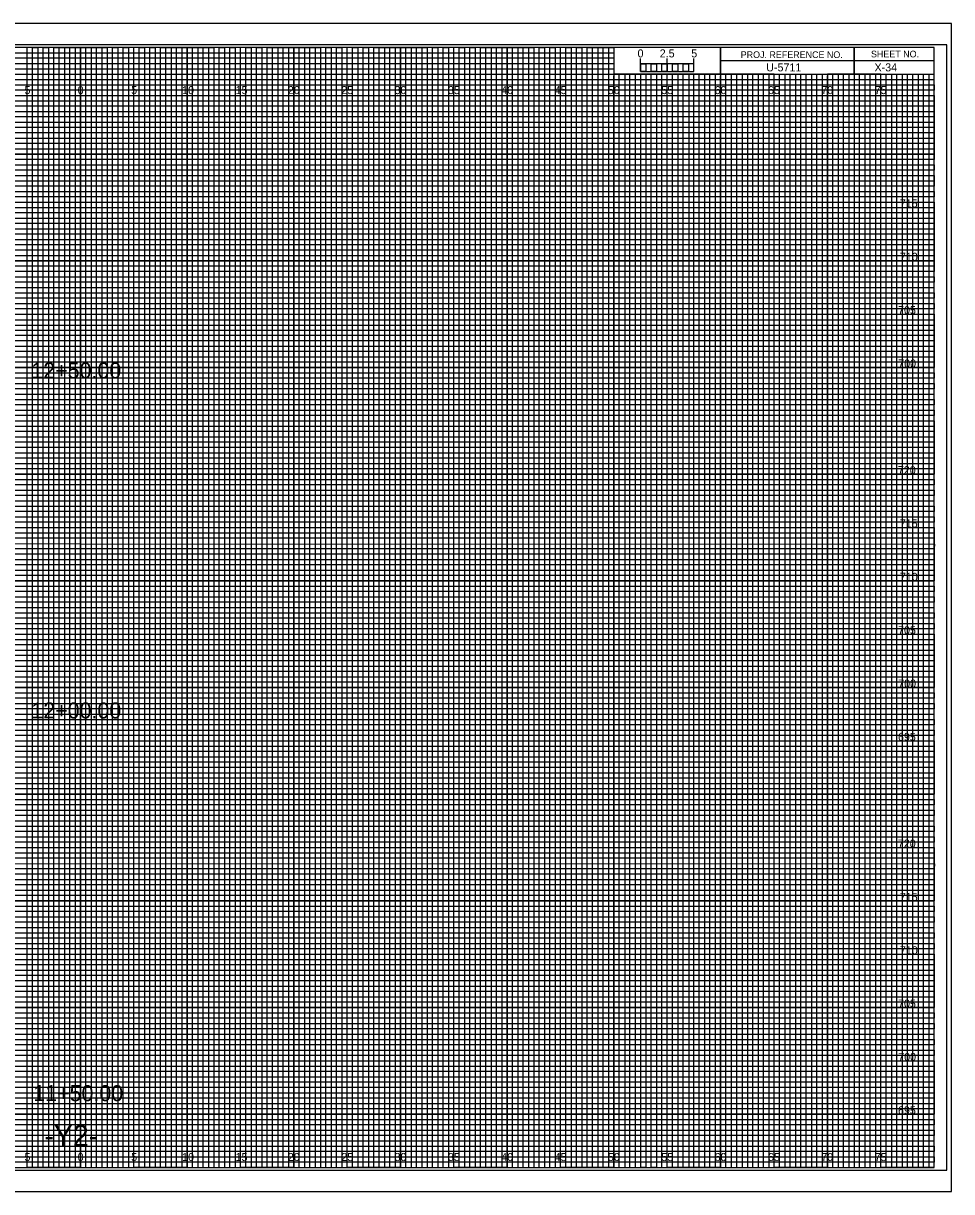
# Model space of a CAD drawing. Extents: x -7 to 162, y -2 to 107.
# Drawn here: x 74.6 to 161.7, y -2.2 to 107.2 of the extents above; entities that cross this region are included whole.
import ezdxf

# ---------------------------------------------------------------- set-up
doc = ezdxf.new("R2010")
doc.units = 0
for name, color, linetype in [('Exist Cross Section Cell', 7, 'Continuous'), ('Exist XS Center Line Elevation Label', 7, 'Continuous'), ('Exist XS Ground Line', 7, 'Continuous'), ('Prop CMT Pvmt Course 1', 7, 'Continuous'), ('Prop CMT Pvmt Course 2', 7, 'Continuous'), ('Prop CMT Pvmt Course 3', 7, 'Continuous'), ('Prop CMT Pvmt Surface', 7, 'Continuous'), ('Prop CMT Pvmt Surface Shoulder', 7, 'Continuous'), ('Prop CMT Shld Paved Course 1', 7, 'Continuous'), ('Prop CMT Shld Paved Course 2', 7, 'Continuous'), ('Prop CMT Shld Paved Course 3', 7, 'Continuous'), ('Prop CMT Slope Grass', 7, 'Continuous'), ('Prop CMT Subgrade Earthwork', 7, 'Continuous'), ('Prop XS Ditch Standard Text', 7, 'Continuous'), ('Prop XS SE Text', 7, 'Continuous'), ('Prop XS Side Slope Text', 7, 'Continuous'), ('Scratch_Level_7', 7, 'Continuous')]:
    doc.layers.add(name, color=color, linetype=linetype)

msp = doc.modelspace()

# ---------------------------------------------------------------- linework, layer by layer
at = {"layer": 'Exist XS Center Line Elevation Label'}
for points in [[(72.5, 0), (77.5, 0), (77.5, 105), (82.5, 105), (82.5, 0), (87.5, 0), (87.5, 105), (92.5, 105), (92.5, 0), (97.5, 0), (97.5, 105), (102.5, 105), (102.5, 0), (107.5, 0), (107.5, 105), (112.5, 105), (112.5, 0), (117.5, 0), (117.5, 105), (122.5, 105), (122.5, 0), (127.5, 0), (127.5, 105), (129.97, 105), (130, 105), (130, 102.5), (132.5, 102.5), (132.5, 0), (137.5, 0), (137.5, 102.5), (142.5, 102.5), (142.5, 0), (147.5, 0), (147.5, 102.5), (152.5, 102.5), (152.5, 0), (157.5, 0), (157.5, 102.5)], [(0, 102.5), (137.5, 102.5)], [(0, 92.5), (160, 92.5), (160, 97.5), (0, 97.5)], [(0, 82.5), (160, 82.5), (160, 87.5), (0, 87.5)], [(0, 72.5), (160, 72.5), (160, 77.5), (0, 77.5)], [(0, 62.5), (160, 62.5), (160, 67.5), (0, 67.5)], [(0, 52.5), (160, 52.5), (160, 57.5), (0, 57.5)], [(0, 42.5), (160, 42.5), (160, 47.5), (0, 47.5)], [(0, 32.5), (160, 32.5), (160, 37.5), (0, 37.5)], [(0, 22.5), (160, 22.5), (160, 27.5), (0, 27.5)], [(0, 12.5), (160, 12.5), (160, 17.5), (0, 17.5)], [(0, 2.5), (160, 2.5), (160, 7.5), (0, 7.5)]]:
    msp.add_lwpolyline(points, dxfattribs=at)
at = {"layer": 'Exist XS Ground Line'}
for p, q in [((75, 105), (70, 105)), ((75, 0), (75, 105)), ((85, 105), (80, 105)), ((80, 105), (80, 0)), ((85, 0), (85, 105)), ((95, 105), (90, 105)), ((90, 105), (90, 0)), ((95, 0), (95, 105)), ((105, 105), (100, 105)), ((100, 105), (100, 0)), ((105, 0), (105, 105)), ((115, 105), (110, 105)), ((110, 105), (110, 0)), ((115, 0), (115, 105)), ((125, 105), (120, 105)), ((120, 105), (120, 0)), ((125, 0), (125, 105)), ((130, 105), (130, 0)), ((135, 0), (135, 102.5)), ((145, 102.5), (140, 102.5)), ((140, 102.5), (140, 0)), ((145, 0), (145, 102.5)), ((155, 102.5), (150, 102.5)), ((150, 102.5), (150, 0)), ((155, 0), (155, 102.5)), ((80, 0), (75, 0)), ((90, 0), (85, 0)), ((100, 0), (95, 0)), ((110, 0), (105, 0)), ((120, 0), (115, 0)), ((130, 0), (125, 0)), ((140, 0), (135, 0)), ((150, 0), (145, 0)), ((160, 0), (155, 0)), ((160, 0), (160, 0))]:
    msp.add_line(p, q, dxfattribs=at)
for points in [[(0, 100), (160, 100), (160, 95), (0, 95)], [(0, 90), (160, 90), (160, 85), (0, 85)], [(0, 80), (160, 80), (160, 75), (0, 75)], [(0, 70), (160, 70), (160, 65), (0, 65)], [(0, 60), (160, 60), (160, 55), (0, 55)], [(0, 50), (160, 50), (160, 45), (0, 45)], [(0, 40), (160, 40), (160, 35), (0, 35)], [(0, 30), (160, 30), (160, 25), (0, 25)], [(0, 20), (160, 20), (160, 15), (0, 15)], [(0, 10), (160, 10), (160, 5), (0, 5)]]:
    msp.add_lwpolyline(points, dxfattribs=at)
at = {"layer": 'Prop CMT Pvmt Course 2'}
msp.add_lwpolyline([(-6.7, -2.25), (161.65, -2.25), (161.65, 107.25), (-6.7, 107.25)], close=True, dxfattribs=at)
at = {"layer": 'Prop CMT Pvmt Course 3'}
msp.add_lwpolyline([(-5.4, -0.25), (161.2, -0.25), (161.2, 105.25), (-5.4, 105.25)], close=True, dxfattribs=at)
at = {"layer": 'Prop CMT Pvmt Surface'}
for p, q in [((161.65, 107.25), (-6.7, 107.25)), ((-6.7, -2.25), (161.65, -2.25))]:
    msp.add_line(p, q, dxfattribs=at)
at = {"layer": 'Prop CMT Shld Paved Course 1'}
for p, q in [((152.5, 105), (152.5, 102.5)), ((152.5, 102.5), (152.5, 105)), ((160, 103.75), (140, 103.75)), ((140, 103.75), (140, 102.5)), ((140, 102.5), (160, 102.5))]:
    msp.add_line(p, q, dxfattribs=at)
for points in [[(160, 105), (0, 105), (0, 0), (160, 0)], [(140, 105), (130, 105), (130, 102.52), (140, 102.52)], [(160, 105), (140, 105), (140, 102.5), (160, 102.5)]]:
    msp.add_lwpolyline(points, close=True, dxfattribs=at)
at = {"layer": 'Prop CMT Shld Paved Course 2'}
for p, q in [((133.5, 102.5), (133, 102.5)), ((133, 102.5), (133, 0)), ((133.5, 0), (133.5, 102.5)), ((134.5, 102.5), (134, 102.5)), ((134, 102.5), (134, 0)), ((134.5, 0), (134.5, 102.5)), ((133, 0), (132.5, 0)), ((134, 0), (133.5, 0))]:
    msp.add_line(p, q, dxfattribs=at)
for points in [[(75, 0), (75.5, 0), (75.5, 105), (76, 105), (76, 0)], [(76, 0), (76.5, 0), (76.5, 105), (77, 105), (77, 0)], [(77.5, 0), (78, 0), (78, 105), (78.5, 105), (78.5, 0)], [(78.5, 0), (79, 0), (79, 105), (79.5, 105), (79.5, 0)], [(80, 0), (80.5, 0), (80.5, 105), (81, 105), (81, 0)], [(81, 0), (81.5, 0), (81.5, 105), (82, 105), (82, 0)], [(82.5, 0), (83, 0), (83, 105), (83.5, 105), (83.5, 0)], [(83.5, 0), (84, 0), (84, 105), (84.5, 105), (84.5, 0)], [(85, 0), (85.5, 0), (85.5, 105), (86, 105), (86, 0)], [(86, 0), (86.5, 0), (86.5, 105), (87, 105), (87, 0)], [(87.5, 0), (88, 0), (88, 105), (88.5, 105), (88.5, 0)], [(88.5, 0), (89, 0), (89, 105), (89.5, 105), (89.5, 0)], [(90, 0), (90.5, 0), (90.5, 105), (91, 105), (91, 0)], [(91, 0), (91.5, 0), (91.5, 105), (92, 105), (92, 0)], [(92.5, 0), (93, 0), (93, 105), (93.5, 105), (93.5, 0)], [(93.5, 0), (94, 0), (94, 105), (94.5, 105), (94.5, 0)], [(95, 0), (95.5, 0), (95.5, 105), (96, 105), (96, 0)], [(96, 0), (96.5, 0), (96.5, 105), (97, 105), (97, 0)], [(97.5, 0), (98, 0), (98, 105), (98.5, 105), (98.5, 0)], [(98.5, 0), (99, 0), (99, 105), (99.5, 105), (99.5, 0)], [(100, 0), (100.5, 0), (100.5, 105), (101, 105), (101, 0)], [(101, 0), (101.5, 0), (101.5, 105), (102, 105), (102, 0)], [(102.5, 0), (103, 0), (103, 105), (103.5, 105), (103.5, 0)], [(103.5, 0), (104, 0), (104, 105), (104.5, 105), (104.5, 0)], [(105, 0), (105.5, 0), (105.5, 105), (106, 105), (106, 0)], [(106, 0), (106.5, 0), (106.5, 105), (107, 105), (107, 0)], [(107.5, 0), (108, 0), (108, 105), (108.5, 105), (108.5, 0)], [(108.5, 0), (109, 0), (109, 105), (109.5, 105), (109.5, 0)], [(110, 0), (110.5, 0), (110.5, 105), (111, 105), (111, 0)], [(111, 0), (111.5, 0), (111.5, 105), (112, 105), (112, 0)], [(112.5, 0), (113, 0), (113, 105), (113.5, 105), (113.5, 0)], [(113.5, 0), (114, 0), (114, 105), (114.5, 105), (114.5, 0)], [(115, 0), (115.5, 0), (115.5, 105), (116, 105), (116, 0)], [(116, 0), (116.5, 0), (116.5, 105), (117, 105), (117, 0)], [(117.5, 0), (118, 0), (118, 105), (118.5, 105), (118.5, 0)], [(118.5, 0), (119, 0), (119, 105), (119.5, 105), (119.5, 0)], [(120, 0), (120.5, 0), (120.5, 105), (121, 105), (121, 0)], [(121, 0), (121.5, 0), (121.5, 105), (122, 105), (122, 0)], [(122.5, 0), (123, 0), (123, 105), (123.5, 105), (123.5, 0)], [(123.5, 0), (124, 0), (124, 105), (124.5, 105), (124.5, 0)], [(125, 0), (125.5, 0), (125.5, 105), (126, 105), (126, 0)], [(126, 0), (126.5, 0), (126.5, 105), (127, 105), (127, 0)], [(127.5, 0), (128, 0), (128, 105), (128.5, 105), (128.5, 0)], [(128.5, 0), (129, 0), (129, 105), (129.5, 105), (129.5, 0)], [(130, 0), (130.5, 0), (130.5, 102.5), (131.01, 102.5), (131.01, 0)], [(131, 0), (131.5, 0), (131.5, 102.5), (132, 102.5), (132, 0)], [(135, 0), (135.49, 0), (135.49, 102.5), (136, 102.5), (136, 0)], [(136, 0), (136.5, 0), (136.5, 102.5), (137.03, 102.5), (137.03, 0)], [(137.5, 0), (138, 0), (138, 102.5), (138.5, 102.5), (138.5, 0)], [(138.5, 0), (139, 0), (139, 102.5), (139.5, 102.5), (139.5, 0)], [(140, 0), (140.5, 0), (140.5, 102.5), (141, 102.5), (141, 0)], [(141, 0), (141.5, 0), (141.5, 102.5), (142, 102.5), (142, 0)], [(142.5, 0), (143, 0), (143, 102.5), (143.5, 102.5), (143.5, 0)], [(143.5, 0), (144, 0), (144, 102.5), (144.5, 102.5), (144.5, 0)], [(145, 0), (145.5, 0), (145.5, 102.5), (146, 102.5), (146, 0)], [(146, 0), (146.5, 0), (146.5, 102.5), (147, 102.5), (147, 0)], [(147.5, 0), (148, 0), (148, 102.5), (148.5, 102.5), (148.5, 0)], [(148.5, 0), (149, 0), (149, 102.5), (149.5, 102.5), (149.5, 0)], [(150, 0), (150.5, 0), (150.5, 102.5), (151, 102.5), (151, 0)], [(151, 0), (151.5, 0), (151.5, 102.5), (152, 102.5), (152, 0)], [(152.5, 0), (153, 0), (153, 102.5), (153.5, 102.5), (153.5, 0)], [(153.5, 0), (154, 0), (154, 102.5), (154.5, 102.5), (154.5, 0)], [(155, 0), (155.5, 0), (155.5, 102.5), (156, 102.5), (156, 0)], [(156, 0), (156.5, 0), (156.5, 102.5), (157, 102.5), (157, 0)], [(157.5, 0), (158, 0), (158, 102.5), (158.5, 102.5), (158.5, 0)], [(158.5, 0), (159, 0), (159, 102.5), (159.5, 102.5), (159.5, 0)]]:
    msp.add_lwpolyline(points, dxfattribs=at)
at = {"layer": 'Prop CMT Shld Paved Course 3'}
for p, q in [((132.5, 102.75), (132.5, 103.95)), ((132.5, 103.45), (132.5, 103.95)), ((135, 102.75), (135, 103.95)), ((137.5, 102.75), (137.5, 103.95)), ((137.5, 103.45), (137.5, 103.95))]:
    msp.add_line(p, q, dxfattribs=at)
for points in [[(137.5, 103.45), (132.5, 103.45), (132.5, 102.75), (137.5, 102.75)], [(132.5, 103.45), (133, 103.45), (133, 102.75), (132.5, 102.75)], [(133.5, 103.45), (134, 103.45), (134, 102.75), (133.5, 102.75)], [(134.5, 103.45), (135, 103.45), (135, 102.75), (134.5, 102.75)], [(135.5, 103.45), (136, 103.45), (136, 102.75), (135.5, 102.75)], [(136.5, 103.45), (137, 103.45), (137, 102.75), (136.5, 102.75)]]:
    msp.add_lwpolyline(points, close=True, dxfattribs=at)
at = {"layer": 'Prop CMT Subgrade Earthwork'}
for p, q in [((75, 0), (75, 105)), ((80, 0), (80, 105)), ((85, 0), (85, 105)), ((90, 0), (90, 105)), ((95, 0), (95, 105)), ((100, 0), (100, 105)), ((105, 0), (105, 105)), ((110, 0), (110, 105)), ((115, 0), (115, 105)), ((120, 0), (120, 105)), ((125, 0), (125, 105)), ((130, 0), (130, 102.34)), ((135, 0), (135, 102.34)), ((140, 0), (140, 102.34)), ((145, 0), (145, 102.34)), ((150, 0), (150, 102.34)), ((155, 0), (155, 102.34)), ((0, 100), (160, 100)), ((0, 95), (160, 95)), ((0, 90), (160, 90)), ((0, 85), (160, 85)), ((0, 80), (160, 80)), ((0, 75), (160, 75)), ((0, 70), (160, 70)), ((0, 65), (160, 65)), ((0, 60), (160, 60)), ((0, 55), (160, 55)), ((0, 50), (160, 50)), ((0, 45), (160, 45)), ((0, 40), (160, 40)), ((0, 35), (160, 35)), ((0, 30), (160, 30)), ((0, 25), (160, 25)), ((0, 20), (160, 20)), ((0, 15), (160, 15)), ((0, 10), (160, 10)), ((0, 5), (160, 5))]:
    msp.add_line(p, q, dxfattribs=at)
at = {"layer": 'Scratch_Level_7'}
for p, q in [((0, 104.5), (130, 104.5)), ((130, 104.5), (130, 103.99)), ((130, 103.99), (0, 103.99)), ((0, 103.5), (130, 103.5)), ((130, 102.95), (0, 102.95)), ((130, 103.5), (130, 102.95)), ((0, 102), (160, 102))]:
    msp.add_line(p, q, dxfattribs=at)
for points in [[(0, 101.5), (135, 101.5), (160, 101.5), (160, 101), (0, 101)], [(0, 100.5), (160, 100.5), (160, 99.5), (0, 99.5)], [(0, 99), (160, 99), (160, 98.5), (0, 98.49)], [(0, 98), (160, 98), (160, 97), (0, 97)], [(0, 96.5), (160, 96.5), (160, 96), (0, 96)], [(0, 95.5), (160, 95.5), (160, 94.5), (0, 94.5)], [(0, 94), (160, 94), (160, 93.5), (0, 93.5)], [(0, 93), (160, 93), (160, 92), (0, 92)], [(0, 91.5), (160, 91.5), (160, 91), (0, 91)], [(0, 90.5), (160, 90.5), (160, 89.5), (0, 89.5)], [(0, 89), (160, 89), (160, 88.5), (0, 88.5)], [(0, 88), (160, 88), (160, 86.98), (160, 86.5), (160, 86), (0, 86)], [(0, 87), (160, 87), (160, 86.5), (0, 86.5)], [(0, 85.5), (160, 85.5), (160, 84.5), (0, 84.52)], [(0, 84.52), (160, 84.5), (160, 84), (0, 84)], [(0, 83.5), (160, 83.5), (160, 83), (0, 83)], [(0, 82), (160, 82), (160, 81.5), (0, 81.5)], [(0, 81), (160, 81), (160, 80.5), (0, 80.5)], [(-0.04, 79.45), (160, 79.45), (160, 78.94), (-0.04, 78.94)], [(0, 78.5), (160, 78.5), (160, 78), (0, 78)], [(0, 77), (160, 77), (160, 76.5), (0, 76.5)], [(0, 76), (160, 76), (160, 75.5), (0, 75.5)], [(0, 74.5), (160, 74.5), (160, 74), (0, 74)], [(0, 73.5), (160, 73.5), (160, 73), (0, 73)], [(0, 72), (160, 72), (160, 71.5), (0, 71.5)], [(0, 71), (160, 71), (160, 70.5), (0, 70.5)], [(0, 69.5), (160, 69.5), (160, 68.99), (0, 69)], [(0, 68.5), (160, 68.5), (160, 68), (0, 68)], [(0, 67), (160, 67), (160, 66.5), (0, 66.5)], [(0, 66), (160, 66), (160, 65.5), (0, 65.5)], [(0, 64.5), (160, 64.5), (160, 64), (0, 64)], [(0, 63.5), (160, 63.5), (160, 63), (0, 63)], [(0, 62), (160, 62), (160, 61.5), (0, 61.5)], [(0, 61), (160, 61), (160, 60.5), (0, 60.5)], [(0, 59.5), (160, 59.5), (160, 59), (0, 59)], [(0, 58.5), (160.03, 58.45), (160, 58), (0, 58)], [(0, 57), (160, 57), (160, 56.5), (0, 56.5)], [(0, 56), (160, 56), (160, 55.5), (0, 55.5)], [(0, 54.5), (160, 54.5), (160, 54), (0, 54)], [(0, 53.5), (160, 53.5), (160, 53), (0, 53)], [(0, 52), (160, 52), (160, 51.5), (0, 51.5)], [(0, 51), (160, 51), (160, 50.5), (0, 50.5)], [(0, 49.5), (160, 49.5), (160, 49), (0, 49)], [(0, 48.5), (160, 48.5), (160, 48), (0, 48)], [(0, 47), (160, 47), (160, 46.5), (0, 46.5)], [(0, 46), (160, 46), (160, 45.5), (0, 45.5)], [(0, 44.5), (160, 44.5), (160, 44), (0, 44)], [(0, 43.5), (160, 43.5), (160, 43), (0, 43)], [(0, 42), (160, 42), (160, 41.5), (0, 41.5)], [(0, 41), (160, 41), (160, 40.5), (0, 40.5)], [(0, 39.5), (160, 39.5), (160, 38.99), (0, 39)], [(0, 38.5), (160, 38.5), (160, 38), (0, 38)], [(0, 37), (160, 37), (160, 36.5), (0, 36.5)], [(0, 36), (160, 36), (160, 35.5), (0, 35.5)], [(0, 34.5), (160, 34.5), (160, 34), (0, 34)], [(0, 33.5), (160, 33.5), (160, 33), (0, 33)], [(0, 32), (160, 32), (160, 31.5), (0, 31.5)], [(0, 31), (160, 31), (160, 30.5), (0, 30.5)], [(0, 29.5), (160, 29.5), (160, 29), (0, 29)], [(0, 28.5), (160.03, 28.46), (160, 28), (0, 28)], [(0, 27), (160, 27), (160, 26.5), (0, 26.5)], [(0, 26), (160, 26), (160, 25.5), (0, 25.5)], [(0, 24.5), (160, 24.5), (160, 24), (0, 24)], [(0, 23.5), (160, 23.5), (160, 23), (0, 23)], [(0, 22), (160, 22), (160, 21.5), (0, 21.5)], [(0, 21), (160, 21), (160, 20.5), (0, 20.5)], [(0, 19.5), (160, 19.5), (160, 19), (0, 19)], [(0, 18.5), (160, 18.5), (160, 18), (0, 18)], [(0, 17), (160, 17), (160, 16.5), (0, 16.5)], [(0, 16), (160, 16), (160, 15.5), (0, 15.5)], [(0, 14.5), (160, 14.5), (160, 14), (0, 14)], [(0, 13.5), (160, 13.5), (160, 13), (0, 13)], [(0, 12), (160, 12), (160, 11.5), (0, 11.5)], [(0, 11), (160, 11), (160, 10.5), (0, 10.5)], [(0, 9.5), (160, 9.5), (160, 9), (0, 9)], [(0, 8.5), (160, 8.5), (160, 8), (0, 8)], [(0, 7), (160, 7), (160, 6.5), (0, 6.5)], [(0, 6), (160, 6), (160, 5.5), (0, 5.5)], [(0, 4.5), (160, 4.5), (160, 4), (0, 4)], [(0, 3.5), (160, 3.5), (160, 3), (0, 3)], [(0, 2), (160, 2), (160, 1.5), (0, 1.5)], [(0, 1), (160, 1), (160, 0.5), (0, 0.5)]]:
    msp.add_lwpolyline(points, dxfattribs=at)

# ---------------------------------------------------------------- texts
at = {"layer": 'Exist Cross Section Cell'}
for s, p in [('5', (74.74, 100.62)), ('0', (79.73, 100.62)), ('0', (79.73, 100.62)), ('5', (84.74, 100.62)), ('10', (89.52, 100.62)), ('15', (94.53, 100.62)), ('20', (99.43, 100.62)), ('25', (104.44, 100.62)), ('30', (109.43, 100.62)), ('35', (114.44, 100.62)), ('40', (119.43, 100.62)), ('45', (124.44, 100.62)), ('50', (129.43, 100.62)), ('55', (134.44, 100.62)), ('60', (139.43, 100.62)), ('65', (144.44, 100.62)), ('70', (149.43, 100.62)), ('75', (154.44, 100.62)), ('5', (74.74, 0.62)), ('0', (79.73, 0.62)), ('0', (79.73, 0.62)), ('5', (84.74, 0.62)), ('10', (89.52, 0.62)), ('15', (94.53, 0.62)), ('20', (99.43, 0.62)), ('25', (104.44, 0.62)), ('30', (109.43, 0.62)), ('35', (114.44, 0.62)), ('40', (119.43, 0.62)), ('45', (124.44, 0.62)), ('50', (129.43, 0.62)), ('55', (134.44, 0.62)), ('60', (139.43, 0.62)), ('65', (144.44, 0.62)), ('70', (149.43, 0.62)), ('75', (154.44, 0.62))]:
    msp.add_text(s, height=0.75, dxfattribs=at).set_placement(p)
at = {"layer": 'Prop CMT Pvmt Course 1'}
for s, p in [('12+50.00', (75.39, 73.97)), ('12+00.00', (75.39, 42.1)), ('11+50.00', (75.57, 6.23))]:
    msp.add_text(s, height=1.5, dxfattribs=at).set_placement(p)
at = {"layer": 'Prop CMT Pvmt Surface Shoulder'}
for s, p in [('715', (156.79, 90)), ('710', (156.8, 85)), ('705', (156.63, 80)), ('700', (156.64, 75)), ('720', (156.61, 65)), ('715', (156.79, 60)), ('710', (156.8, 55)), ('705', (156.63, 50)), ('700', (156.64, 45)), ('695', (156.62, 40)), ('720', (156.61, 30)), ('715', (156.79, 25)), ('710', (156.8, 20)), ('705', (156.63, 15)), ('700', (156.64, 10)), ('695', (156.62, 5))]:
    msp.add_text(s, height=0.75, dxfattribs=at).set_placement(p)
at = {"layer": 'Prop CMT Shld Paved Course 1'}
for s, p in [('PROJ. REFERENCE NO.', (141.88, 104)), ('SHEET NO.', (154.09, 104.06))]:
    msp.add_text(s, height=0.625, dxfattribs=at).set_placement(p)
at = {"layer": 'Prop CMT Shld Paved Course 3'}
msp.add_text('0', height=0.75, dxfattribs=at).set_placement((132.21, 104.06))
at = {"layer": 'Prop CMT Slope Grass'}
msp.add_text('X-34', height=0.75, dxfattribs=at).set_placement((154.42, 102.75))
at = {"layer": 'Prop XS Ditch Standard Text'}
for s, p in [('2.5', (134.29, 104.06)), ('5', (137.24, 104.06))]:
    msp.add_text(s, height=0.75, dxfattribs=at).set_placement(p)
at = {"layer": 'Prop XS SE Text'}
msp.add_text('-Y2-', height=2, dxfattribs=at).set_placement((76.6, 2))
at = {"layer": 'Prop XS Side Slope Text'}
msp.add_text('U-5711', height=0.75, dxfattribs=at).set_placement((144.27, 102.75))

doc.saveas('drawing.dxf')
